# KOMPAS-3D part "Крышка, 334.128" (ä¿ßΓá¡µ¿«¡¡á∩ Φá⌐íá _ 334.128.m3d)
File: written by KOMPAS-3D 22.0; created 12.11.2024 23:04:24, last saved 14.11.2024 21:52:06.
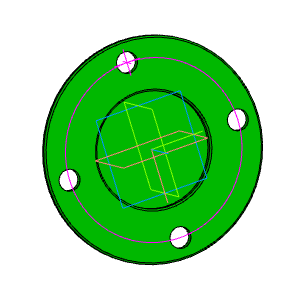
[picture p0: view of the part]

Document properties: Автор: aleksander.larionov.10@gmail.com; Полное имя файла: C:\Мои папки\Работа\Крышки, фланцы\334.128\Дистанционная шайба _ 334.128.m3d

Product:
- Part/product: Крышка  | designation 334.128
    Материал: Сталь 45 ГОСТ 1050-2013 (density 7810 kg/m3)
    Масса: 0.45945

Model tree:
1. Эскиз:1
2. Элемент вращения:1
     Угол 1 = 360
3. Фаска:1  (with: Элемент вращения:1)
     Угол = 45; Длина 1 = 1; Длина 2 = 1
4. Фаска:2  (with: Элемент вращения:1)
     Угол = 45; Длина 1 = 1; Длина 2 = 1
5. Эскиз:2  (with: Элемент вращения:1, Фаска:1)
6. Отверстие:1  (with: Элемент вращения:1)
     Глубина выреза = 40; Диаметр отверстия = 12; Угол конуса дна = 118; Расстояние 2 = -50
7. Массив по концентрической сетке:1  (with: Отверстие:1)  (labels: Сталь 45 ГОСТ 1050-2013)  (4 pattern instances)
     Шаг 2 = 360

Expressions: 124/2; 64/2; 74/2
